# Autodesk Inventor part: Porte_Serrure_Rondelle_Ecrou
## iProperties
Created: 2009-01
Part Number: Porte_Serrure_Rondelle_Ecrou
Document SubType Name: Modeling
Designer: claivier
Author: claivier
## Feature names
1. Base1
